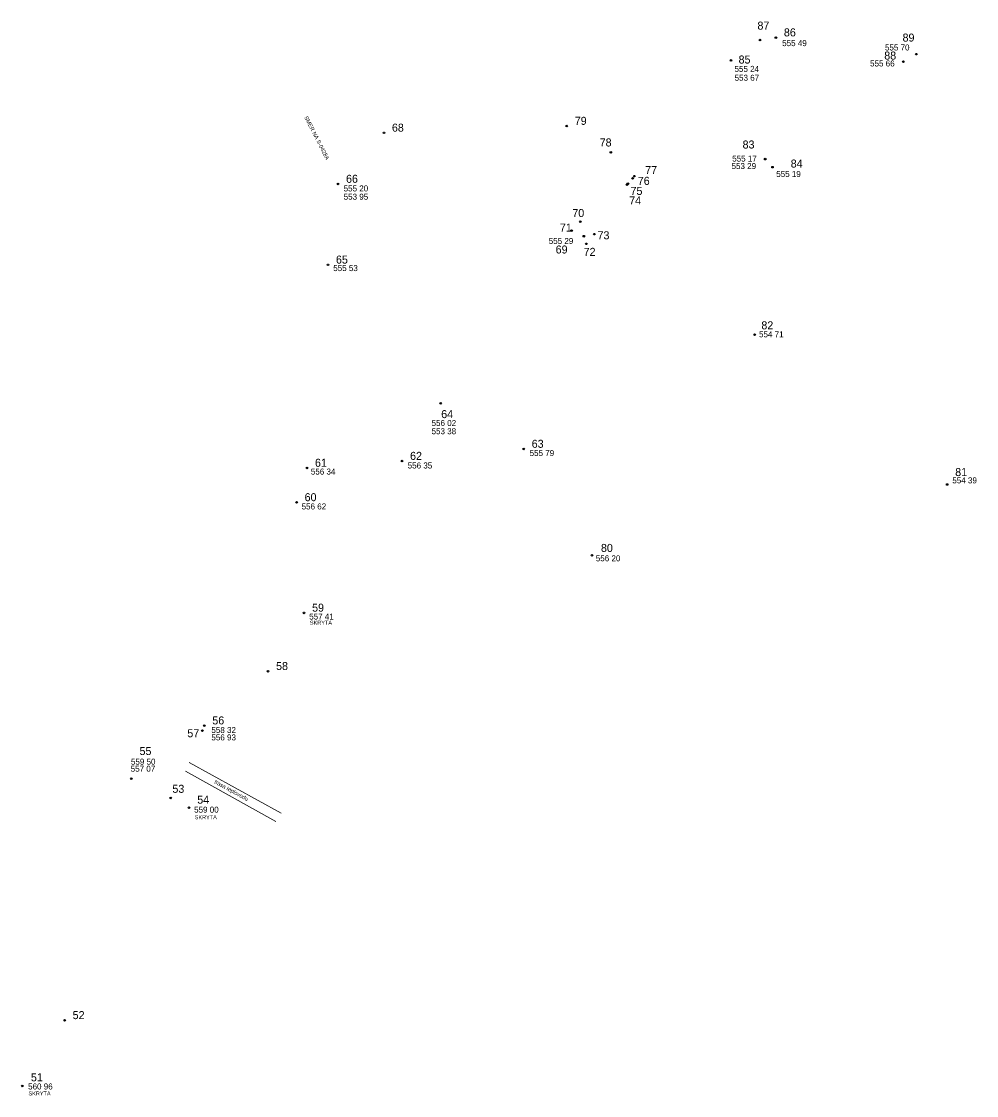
# Model space of a CAD drawing. Extents: x -710806 to -710046, y -1116918 to -1116046.
# Drawn here: x -710489.8 to -710370.5, y -1116617.9 to -1116483.7 of the extents above; entities that cross this region are included whole.
import ezdxf
from ezdxf.enums import TextEntityAlignment as Align

# ---------------------------------------------------------------- set-up
doc = ezdxf.new("R2010")
doc.units = 0
doc.header["$LTSCALE"] = 0.4
doc.header["$PDMODE"] = 32
doc.header["$PDSIZE"] = 0.2
for name, color, linetype in [('43', 7, 'Continuous'), ('55', 7, 'Continuous'), ('56', 7, 'Continuous')]:
    doc.layers.add(name, color=color, linetype=linetype)
doc.layers.add('63', color=7, linetype='Continuous', lineweight=13)

msp = doc.modelspace()

# ---------------------------------------------------------------- linework, layer by layer
at = {"layer": '56'}
for p in [(-710397.583, -1116486.044), (-710395.596, -1116485.734), (-710378.062, -1116487.8), (-710401.2, -1116488.589), (-710379.666, -1116488.751), (-710421.722, -1116496.781), (-710444.563, -1116497.633), (-710416.216, -1116500.068), (-710396.928, -1116500.912), (-710396.022, -1116501.92), (-710450.296, -1116504.021), (-710414.085, -1116503.985), (-710413.494, -1116503.32), (-710413.273, -1116503.047), (-710414.185, -1116504.11), (-710420.036, -1116508.736), (-710421.123, -1116509.844), (-710419.591, -1116510.546), (-710418.278, -1116510.292), (-710419.264, -1116511.497), (-710451.551, -1116514.116), (-710398.25, -1116522.847), (-710437.461, -1116531.408), (-710427.099, -1116537.123), (-710442.295, -1116538.632), (-710454.176, -1116539.496), (-710374.198, -1116541.558), (-710455.469, -1116543.796), (-710418.577, -1116550.402), (-710454.536, -1116557.596), (-710459.034, -1116564.885), (-710467.241, -1116572.309), (-710466.997, -1116571.678), (-710476.116, -1116578.317), (-710471.198, -1116580.714), (-710468.921, -1116581.933), (-710484.445, -1116608.494), (-710489.738, -1116616.69)]:
    msp.add_point(p, dxfattribs=at)
at = {"layer": '63'}
for p, q in [((-710468.87, -1116576.28), (-710457.392, -1116582.603)), ((-710469.351, -1116577.377), (-710458.066, -1116583.665))]:
    msp.add_line(p, q, dxfattribs=at)

# ---------------------------------------------------------------- texts
at = {"layer": '43'}
for s, p in [('555 49 ', (-710393.1362, -1116486.8)), ('555 70 ', (-710380.2962, -1116487.343)), ('555 66 ', (-710382.1592, -1116489.338)), ('555 24 ', (-710399.0952, -1116490.017)), ('555 17 ', (-710399.3792, -1116501.219)), ('555 19 ', (-710393.8802, -1116503.144)), ('555 20 ', (-710447.9192, -1116504.95)), ('555 29 ', (-710422.2982, -1116511.518)), ('555 53 ', (-710449.2172, -1116514.902)), ('554 71 ', (-710396.0282, -1116523.167)), ('556 02 ', (-710436.9372, -1116534.254)), ('555 79 ', (-710424.6872, -1116538.005)), ('556 35 ', (-710439.9182, -1116539.558)), ('556 34 ', (-710452.0162, -1116540.319)), ('554 39 ', (-710371.8802, -1116541.419)), ('556 62 ', (-710453.1702, -1116544.676)), ('556 20 ', (-710416.4172, -1116551.152)), ('557 41 ', (-710452.2212, -1116558.429)), ('558 32 ', (-710464.4392, -1116572.607)), ('559 50 ', (-710474.4912, -1116576.557)), ('559 00 ', (-710466.5992, -1116582.552)), ('560 96 ', (-710487.3332, -1116617.13))]:
    msp.add_text(s, height=0.75, dxfattribs=at).set_placement(p, align=Align.CENTER)
for s, p in [('553 67', (-710400.755, -1116491.126)), ('553 29', (-710401.137, -1116502.155)), ('553 95', (-710449.59, -1116505.982)), ('553 38', (-710438.609, -1116535.277)), ('556 93', (-710466.112, -1116573.527)), ('557 07', (-710476.195, -1116577.439))]:
    msp.add_text(s, height=0.75, dxfattribs=at).set_placement(p)
at = {"layer": '55'}
for s, p in [('87', (-710397.9, -1116484.735)), ('86', (-710394.596, -1116485.584)), ('89', (-710379.772, -1116486.231)), ('88', (-710382.06, -1116488.474)), ('85', (-710400.257, -1116488.973)), ('79', (-710420.722, -1116496.631)), ('68', (-710443.563, -1116497.483)), ('78', (-710417.611, -1116499.331)), ('83', (-710399.757, -1116499.59)), ('84', (-710393.744, -1116501.967)), ('77', (-710411.926, -1116502.775)), ('66', (-710449.296, -1116503.871)), ('76', (-710412.852, -1116504.129)), ('75', (-710413.756, -1116505.389)), ('74', (-710413.922, -1116506.577)), ('70', (-710421.024, -1116508.147)), ('71', (-710422.583, -1116509.967)), ('73', (-710417.879, -1116510.929)), ('69', (-710423.107, -1116512.705)), ('72', (-710419.612, -1116512.997)), ('65', (-710450.551, -1116513.966)), ('82', (-710397.411, -1116522.174)), ('64', (-710437.408, -1116533.269)), ('63', (-710426.099, -1116536.973)), ('62', (-710441.295, -1116538.482)), ('61', (-710453.176, -1116539.346)), ('81', (-710373.197, -1116540.505)), ('60', (-710454.469, -1116543.646)), ('80', (-710417.448, -1116549.983)), ('59', (-710453.536, -1116557.446)), ('58', (-710458.034, -1116564.735)), ('56', (-710465.997, -1116571.528)), ('57', (-710469.119, -1116573.134)), ('55', (-710475.094, -1116575.355)), ('53', (-710470.986, -1116580.072)), ('54', (-710467.881, -1116581.428)), ('52', (-710483.445, -1116608.344)), ('51', (-710488.66, -1116616.115))]:
    msp.add_text(s, height=1, dxfattribs=at).set_placement(p)
at = {"layer": '63'}
for s, rotation, p in [('SMER NA S-0428A', 297, (-710454.531, -1116495.694)), ('trasa teplovodu', 331.2, (-710465.799, -1116578.851))]:
    msp.add_text(s, height=0.5, rotation=rotation, dxfattribs=at).set_placement(p)
for p in [(-710453.808, -1116559.072), (-710468.196, -1116583.374), (-710488.961, -1116617.879)]:
    msp.add_text('SKRYTA', height=0.5, dxfattribs=at).set_placement(p)

doc.saveas('drawing.dxf')
